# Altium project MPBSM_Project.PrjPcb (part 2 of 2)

## Sheet MPBSM_PowerDistribution.SchDoc: Power distribution subcircuit
size 431 x 279 mm; Date: Not shown in title block; ApprovedBy: Not shown in title block; CheckedBy: Not shown in title block; Author: Not shown in title block; CompanyName: Not shown in title block; DrawnBy: Ricky Zepeda; Engineer: Not shown in title block; Organization: Not shown in title block; Address1: Not shown in title block; Address2: Not shown in title block; Address3: Not shown in title block; Address4: Not shown in title block; DocumentNumber: 2; Revision: Use project parameter SCH_Rev; SheetNumber: 2; SheetTotal: 12; PageSetup: Record=PageOptions¦CenterHorizontal=True¦CenterVertical=True¦PrintScale=0.62¦XCorrection=1.00¦YCorrection=1.00¦PrintKind=0¦BorderSize=5000000¦LeftOffset=0¦BottomOffset=0¦Orientation=2¦PaperLength=1000¦PaperWidth=1000¦Scale=100¦PaperSource=15¦PrintQuality=600¦MediaType=1¦DitherType=10¦PaperKind=Letter¦PrintScaleMode=1
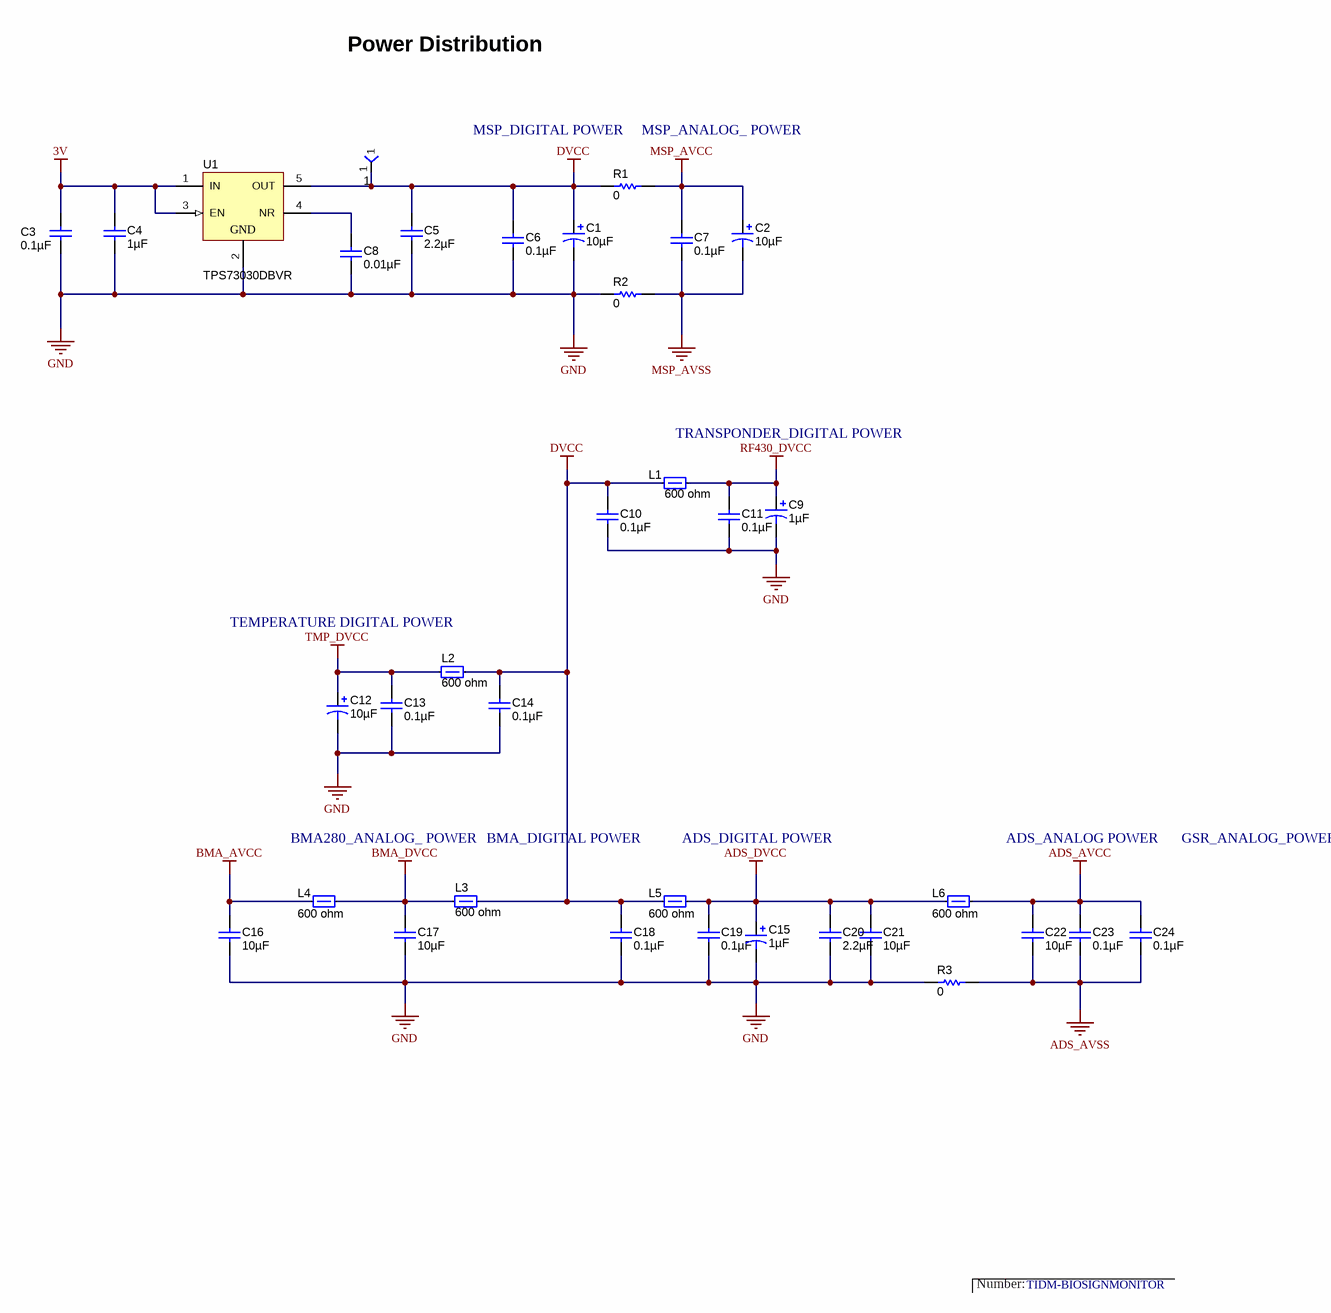
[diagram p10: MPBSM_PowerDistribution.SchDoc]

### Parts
1  TP-025-SMT  [TP_25MIL-SMT]  (value not drawn)
C1  ValueDisplayed: 10µF  [3216-18]  (hidden comment: 293D106X9010A2TE3)
C2  ValueDisplayed: 10µF  [3216-18]  (hidden comment: 293D106X9010A2TE3)
C3  ValueDisplayed: 0.1µF  [0402]  (hidden comment: C1005X5R1A104K)
C4  ValueDisplayed: 1µF  [0402]  (hidden comment: C1005X5R0J105M)
C5  ValueDisplayed: 2.2µF  [0402]  (hidden comment: C1005X5R1C225K050BC)
C6  ValueDisplayed: 0.1µF  [0402]  (hidden comment: C1005X5R1A104K)
C7  ValueDisplayed: 0.1µF  [0402]  (hidden comment: C1005X5R1A104K)
C8  ValueDisplayed: 0.01µF  [0402]  (hidden comment: C1005X7R1E103K)
C9  ValueDisplayed: 1µF  [3216-18]  (hidden comment: 293D105X9016A2TE3)
C10  ValueDisplayed: 0.1µF  [0402]  (hidden comment: C1005X5R1A104K)
C11  ValueDisplayed: 0.1µF  [0402]  (hidden comment: C1005X5R1A104K)
C12  ValueDisplayed: 10µF  [3216-18]  (hidden comment: 293D106X9010A2TE3)
C13  ValueDisplayed: 0.1µF  [0402]  (hidden comment: C1005X5R1A104K)
C14  ValueDisplayed: 0.1µF  [0402]  (hidden comment: C1005X5R1A104K)
C15  ValueDisplayed: 1µF  [3216-18]  (hidden comment: 293D105X9016A2TE3)
C16  ValueDisplayed: 10µF  [0402]  (hidden comment: CL05A106MQ5NUNC)
C17  ValueDisplayed: 10µF  [0402]  (hidden comment: CL05A106MQ5NUNC)
C18  ValueDisplayed: 0.1µF  [0402]  (hidden comment: C1005X5R1A104K)
C19  ValueDisplayed: 0.1µF  [0402]  (hidden comment: C1005X5R1A104K)
C20  ValueDisplayed: 2.2µF  [0402]  (hidden comment: C1005X5R1C225K050BC)
C21  ValueDisplayed: 10µF  [0402]  (hidden comment: CL05A106MQ5NUNC)
C22  ValueDisplayed: 10µF  [0402]  (hidden comment: CL05A106MQ5NUNC)
C23  ValueDisplayed: 0.1µF  [0402]  (hidden comment: C1005X5R1A104K)
C24  ValueDisplayed: 0.1µF  [0402]  (hidden comment: C1005X5R1A104K)
L1  value 600 ohm  [0603]  (hidden comment: BLM18HG601SN1D)
L2  value 600 ohm  [0603]  (hidden comment: BLM18HG601SN1D)
L3  value 600 ohm  [0603]  (hidden comment: BLM18HG601SN1D)
L4  value 600 ohm  [0603]  (hidden comment: BLM18HG601SN1D)
L5  value 600 ohm  [0603]  (hidden comment: BLM18HG601SN1D)
L6  value 600 ohm  [0603]  (hidden comment: BLM18HG601SN1D)
R1  ValueDisplayed: 0  [0402]  (hidden comment: ERJ-2GE0R00X)
R2  ValueDisplayed: 0  [0402]  (hidden comment: ERJ-2GE0R00X)
R3  ValueDisplayed: 0  [0402]  (hidden comment: ERJ-2GE0R00X)
U1  TPS73030DBVR  [DBV0005A_N]

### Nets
3V: C3.1 C4.1 U1.1(IN) U1.3(EN)
ADS_AVCC: C22.1 C23.1 C24.1 L6.2
ADS_AVSS: C22.2 C23.2 C24.2 R3.2
ADS_DVCC: C15.1(+) C19.1 C20.1 C21.1 L5.2 L6.1
BMA_AVCC: C16.1 L4.1
BMA_DVCC: C17.1 L3.2 L4.2
DVCC: 1.1 C1.1(+) C5.1 C6.1 C10.1 C14.1 C18.1 L1.1 L2.1 L3.1 L5.1 R1.1 U1.5(OUT)
GND: C1.2(-) C3.2 C4.2 C5.2 C6.2 C8.2 C9.2(-) C10.2 C11.2 C12.2(-) C13.2 C14.2 C15.2(-) C16.2 C17.2 C18.2 C19.2 C20.2 C21.2 R2.1 R3.1 U1.2(GND)
MSP_AVCC: C2.1(+) C7.1 R1.2
MSP_AVSS: C2.2(-) C7.2 R2.2
RF430_DVCC: C9.1(+) C11.1 L1.2
TMP_DVCC: C12.1(+) C13.1 L2.2
NetC8_1: C8.1 U1.4(NR)

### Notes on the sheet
- Power Distribution
- (near R1) MSP_DIGITAL POWER
- (near R1) MSP_ANALOG_ POWER
- (near L1) TRANSPONDER_DIGITAL POWER
- TEMPERATURE DIGITAL POWER
- BMA280_ANALOG_ POWER
- BMA_DIGITAL POWER
- ADS_DIGITAL POWER
- ADS_ANALOG POWER
- GSR_ANALOG_POWER
- Number:
- TIDM-BIOSIGNMONITOR

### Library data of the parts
1 = TP-025-SMT: Test Point, O.025"; Manufacturer: STD; Value: STD
C1 C2 C12 = 293D106X9010A2TE3: CAP, TA, 10 µF, 10 V, +/- 10%, 3.4 ohm, SMD; Manufacturer: Vishay-Sprague; Polarized: Y; CompType: Capacitor; Value: 10uF; U/M: EA; Cap_F: 0.00001; Tolerance_%: 10; Value1: 3.4 ohm; Value2: 10V; ESR_ohm: 3.4; IRMS_A: 0.15; TaMin_C: -55; TaMax_C: 125; Cap_Case: A
C3 C6 C7 C10 C11 C13 C14 C18 C19 C23 C24 = C1005X5R1A104K: CAP, CERM, 0.1 µF, 10 V, +/- 10%, X5R, 0402; Manufacturer: TDK; Polarized: N; CompType: Capacitor; Value: 0.1uF; U/M: EA; Cap_F: 0.0000001; Tolerance_%: 10; ESR_ohm: 0.0186; Value1: 0.0186 ohm; Value2: 10V; TaMin_C: -55; TaMax_C: 85
C4 = C1005X5R0J105M: CAP, CERM, 1 µF, 6.3 V, +/- 20%, X5R, 0402; Manufacturer: TDK; Polarized: N; CompType: Capacitor; Value: 1uF; U/M: EA; Cap_F: 0.000001; Tolerance_%: 20; ESR_ohm: 0.0079; Value1: 0.0079 ohm; VDC_V: 6.3; Value2: 6.3V; TaMin_C: -55; TaMax_C: 85
C5 C20 = C1005X5R1C225K050BC: CAP, CERM, 2.2 µF, 16 V, +/- 10%, X5R, 0402; Manufacturer: TDK; Polarized: N; CompType: Capacitor; Value: 2.2uF; U/M: EA; Cap_F: 0.0000022; Tolerance_%: 10; Value1: Unknown; VDC_V: 16; Value2: 16V; TaMin_C: -55; TaMax_C: 85
C8 = C1005X7R1E103K: CAP, CERM, 0.01 µF, 25 V, +/- 10%, X7R, 0402; Manufacturer: TDK; Polarized: N; CompType: Capacitor; Value: 0.01uF; U/M: EA; Cap_F: 0.00000001; Tolerance_%: 10; ESR_ohm: 0.0623; Value1: 0.0623 ohm; VDC_V: 25; Value2: 25V; TaMin_C: -55; TaMax_C: 125
C9 C15 = 293D105X9016A2TE3: CAP, TA, 1 µF, 16 V, +/- 10%, 9.3 ohm, SMD; Manufacturer: Vishay-Sprague; Polarized: Y; CompType: Capacitor; Value: 1uF; U/M: EA; Cap_F: 0.000001; Tolerance_%: 10; Value1: 9.3 ohm; VDC_V: 16; Value2: 16V; ESR_ohm: 9.3; IRMS_A: 0.09; TaMin_C: -55; TaMax_C: 125; Cap_Case: A
C16 C17 C21 C22 = CL05A106MQ5NUNC: CAP, CERM, 10 µF, 6.3 V, +/- 20%, X5R, 0402; Manufacturer: Samsung; Polarized: N; CompType: Capacitor; Value: 10uF; U/M: EA; Cap_F: 0.00001; Tolerance_%: 20; Value1: Unknown; VDC_V: 6.3; Value2: 6.3V; TaMin_C: -55; TaMax_C: 85
L1-L6 = BLM18HG601SN1D: Ferrite Bead, 600 ohm @ 100MHz, 0.2A, 0603; Manufacturer: MuRata; Imax_A: 0.2; DCR_ohm: 1; Value1: 1 ohm; ZTyp@100MHz_Ohm: 600; Ztyp@1GHz_Ohm: 700
R1-R3 = ERJ-2GE0R00X: RES, 0, 5%, 0.063 W, 0402; Manufacturer: Panasonic; CompType: Resistor; Value: 0; Value_Code: 0000; Tolerance_%: 5; Power_W: 0.063; Value2: 0.063W; VDC_V: 50; TempCo: 600 ppm/C; EIA_Code: E24; U/M: EA
U1 = TPS73030DBVR: Single Output High PSRR LDO, 200 mA, Fixed 3 V Output, 2.7 to 5.5 V Input, 5-pin SOT-23 (DBV), -40 to 85 degC, Green (RoHS & no Sb/Br); Manufacturer: Texas Instruments; Alternate Manufacturer: None; Alternate PartNumber: Equivalent; Accuracy(%): 2; Fixed Output Options(V): 3V; Iout(Max)(A): 200mA; Iq(Typ)(mA): 170mA; Rating: Catalog; SubFamily: Single Channel LDO; Vdo(Typ)(mV): 120; Vin(Max)(V): 5.5; Vin(Min)(V): 2.7; Vout Adj(Max)(V): 3; CompType: IC; Value: 3V; Value2: 0.12V @ 200mA; Value3: InputVoltage - Up to 5.5V

## Sheet MPBSM_Analog_Connector.SchDoc
size 431 x 279 mm; Date: Not shown in title block; ApprovedBy: Not shown in title block; CheckedBy: Not shown in title block; Author: Not shown in title block; CompanyName: Not shown in title block; Engineer: Not shown in title block; Organization: Not shown in title block; Address1: Not shown in title block; Address2: Not shown in title block; Address3: Not shown in title block; Address4: Not shown in title block; DocumentNumber: 1; Revision: Use project parameter SCH_Rev; SheetNumber: 2; SheetTotal: 3; PageSetup: Record=PageOptions¦CenterHorizontal=True¦CenterVertical=True¦PrintScale=1.00¦XCorrection=1.00¦YCorrection=1.00¦PrintKind=0¦BorderSize=5000000¦LeftOffset=0¦BottomOffset=0¦Orientation=2¦PaperLength=1000¦PaperWidth=1000¦Scale=100¦PaperSource=15¦PrintQuality=600¦MediaType=1¦DitherType=10¦PaperKind=Letter¦PrintScaleMode=1
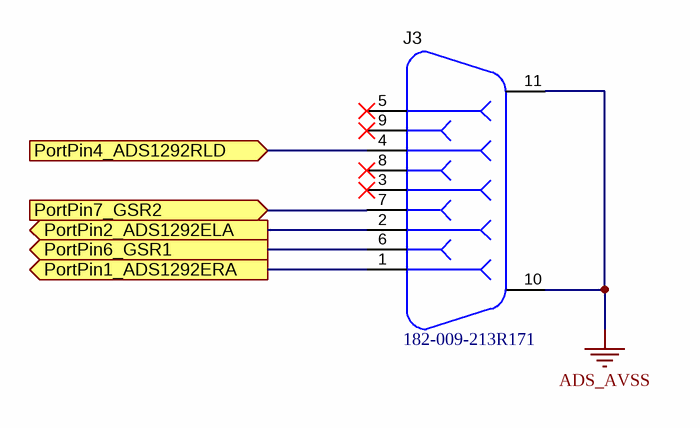
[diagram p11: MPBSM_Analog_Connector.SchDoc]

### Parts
J3  182-009-213R171  [NORCOMP_182-009-213R171]

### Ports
PortPin1_ADS1292ERA (out), PortPin2_ADS1292ELA (out), PortPin4_ADS1292RLD (in), PortPin6_GSR1 (out), PortPin7_GSR2 (in)

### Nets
ADS_AVSS: J3.10 J3.11
ADS1292_ELA: J3.2 ; port PortPin2_ADS1292ELA
ADS1292_ERA: J3.1 ; port PortPin1_ADS1292ERA
ADS1292_RLD: J3.4 ; port PortPin4_ADS1292RLD
EL_GSR1: J3.6 ; port PortPin6_GSR1
EL_GSR2: J3.7 ; port PortPin7_GSR2

Not connected (* = marked no-connect by the designer): J3 3* 5* 8* 9*

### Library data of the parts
J3 = 182-009-213R171: CONN DB9 FEMALE R/A SOLDER TH; Manufacturer: NorComp; SymbolCreator: a0412235; CompType: Connector

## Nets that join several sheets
3V: MPBSM_JTAG_SPYBYWIRE (R4.2 R5.2), MPBSM_BoostConverter (C35.1 R15.2 U5.4), MPBSM_PowerDistribution (C3.1 C4.1 U1.1 U1.3)
ADS_AVCC: MPBSM_GSR (R8.2 U2.5), MPBSM_ECG (5 pins), MPBSM_PowerDistribution (C22.1 C23.1 C24.1 L6.2)
ADS_AVSS: MPBSM_GSR (R9.1 R12.1 U2.2 U3.2), MPBSM_ECG (12 pins), MPBSM_PowerDistribution (C22.2 C23.2 C24.2 R3.2), MPBSM_Analog_Connector (J3.10 J3.11)
ADS_DVCC: MPBSM_ECG (C41.1 C42.1 U8.23), MPBSM_PowerDistribution (6 pins)
DVCC: MPBSM_MSP (6 pins), MPBSM_JTAG_SPYBYWIRE (R6.2), MPBSM_PowerDistribution (13 pins)
GND: MPBSM_MSP (7 pins), MPBSM_JTAG_SPYBYWIRE (C25.2 J1.6 J2.10), MPBSM_Battery (BT1.2 BT2.2 BT3.2 BT4.2), MPBSM_BoostConverter (C34.2 C35.2 R17.1 U5.3), MPBSM_NFC_Trans (9 pins), MPBSM_Temperature (C38.2 U7.2 U7.4), MPBSM_ECG (C41.2 C42.2 U8.24), MPBSM_PowerDistribution (22 pins)
MSP_AVCC: MPBSM_MSP (U9.52), MPBSM_PowerDistribution (C2.1 C7.1 R1.2)
MSP_AVSS: MPBSM_MSP (U9.53 U9.56 U9.59), MPBSM_PowerDistribution (C2.2 C7.2 R2.2)
RF430_DVCC: MPBSM_NFC_Trans (7 pins), MPBSM_PowerDistribution (C9.1 C11.1 L1.2)
TMP_DVCC: MPBSM_Temperature (R18.2), MPBSM_PowerDistribution (C12.1 C13.1 L2.2)
ADS1292_DRDY: MPBSM_MSP (U9.28), MPBSM_ECG (9.1 U8.22)
ADS1292_ELA: MPBSM_Block_Diagram (J4.3 TP4.1), MPBSM_ECG (C52.1 R30.1), MPBSM_Analog_Connector (J3.2)
ADS1292_ERA: MPBSM_Block_Diagram (J4.2 TP3.1), MPBSM_ECG (C48.1 R23.1), MPBSM_Analog_Connector (J3.1)
ADS1292_GPIO1: MPBSM_MSP (U9.9), MPBSM_ECG (6.1 U8.26)
ADS1292_GPIO2: MPBSM_MSP (U9.25), MPBSM_ECG (7.1 U8.25)
ADS1292_MAIN_CLKSEL: MPBSM_MSP (U9.32), MPBSM_ECG (14.1 U8.14)
ADS1292_RESET: MPBSM_MSP (U9.31), MPBSM_ECG (8.1 U8.15)
ADS1292_RLD: MPBSM_Block_Diagram (J4.1 TP5.1), MPBSM_ECG (R22.2), MPBSM_Analog_Connector (J3.4)
ADS1292_SPI_CS: MPBSM_MSP (U9.13), MPBSM_ECG (10.1 U8.18)
ADS1292_SPI_DIN: MPBSM_MSP (U9.15), MPBSM_ECG (12.1 U8.19)
ADS1292_SPI_DOUT: MPBSM_MSP (U9.16), MPBSM_ECG (11.1 U8.21)
ADS1292_SPI_SCLK: MPBSM_MSP (U9.14), MPBSM_ECG (13.1 U8.20)
ADS1292_START: MPBSM_MSP (U9.30), MPBSM_ECG (15.1 U8.16)
BOOST_INPUT: MPBSM_Battery (BT1.1 BT2.1 BT3.1 BT4.1), MPBSM_BoostConverter (C34.1 L7.1 R16.1 U5.1)
EL_GSR1: MPBSM_Block_Diagram (J5.2 TP2.1), MPBSM_GSR (C26.2 R10.1 U2.4), MPBSM_Analog_Connector (J3.6)
EL_GSR2: MPBSM_Block_Diagram (J5.1 TP1.1), MPBSM_GSR (R9.2), MPBSM_Analog_Connector (J3.7)
GSR_ANALOG_OUTPUT: MPBSM_MSP (U9.37), MPBSM_GSR (2.1 C26.1 R10.2 U2.1)
JTAG_TDO/TDI: MPBSM_MSP (U9.20), MPBSM_JTAG_SPYBYWIRE (C25.1 J1.2 J2.2 R6.1)
JTAG_TEST/SBWTCK: MPBSM_MSP (U9.19), MPBSM_JTAG_SPYBYWIRE (R7.2)
MSP_P1.0_INT: MPBSM_MSP (U9.39), MPBSM_NFC_Trans (U4.10)
MSP_P2.6_INT: MPBSM_MSP (U9.8), MPBSM_Temperature (U7.3)
MSP_P4.0_INT: MPBSM_MSP (U9.60), MPBSM_NFC_Trans (U4.9)
MSP_P4.1_INT: MPBSM_MSP (U9.61), MPBSM_NFC_Trans (U4.8)
MSP_P9.3_OUT: MPBSM_MSP (U9.43), MPBSM_NFC_Trans (U4.4)
MSP_UCB0SCL_TMP103_SCL_RF430CL330HCPW_SCL: MPBSM_MSP (R32.2 U9.5), MPBSM_NFC_Trans (U4.11), MPBSM_Temperature (U7.1)
MSP_UCB0SDA_TMP103_SDA_RF430CL330HCPW_SDA: MPBSM_MSP (R31.2 U9.4), MPBSM_NFC_Trans (U4.12), MPBSM_Temperature (U7.6)

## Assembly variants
MPBSM_Project_FR4: not fitted BT1 BT2 J1
MPBSM_Project_Overlay: not fitted BT3 BT4 H1 H2 H3 H4 H5 H6 H7 H8 H9 H10 H11 H12 J2 J2 J3 J4 J5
